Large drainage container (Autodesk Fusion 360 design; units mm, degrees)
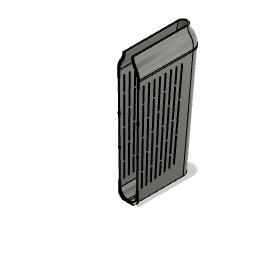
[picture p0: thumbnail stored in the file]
sketch "Schizzo1" plane through (0, 0, 0) normal (0, 1, 0) x axis (1, 0, 0)
  line L1 (12.5, 62.5) -> (12.5, -62.5)
  line L2 (-12.5, -62.5) -> (-12.5, 62.5)
  line L3 (0, 62.5) -> (0, -62.5)
  line L4 (-10, -62.5) -> (-10, 62.5)
  line L5 (10, 62.5) -> (10, -62.5)
  line L6 (0, -75) -> (0, 0)
  line L7 (0, -75) -> (0, 75)
  arc A1 centre (0, 62.5) radius 12.5 clockwise from (-12.5, 62.5) to (12.5, 62.5)
  arc A2 centre (0, -62.5) radius 12.5 clockwise from (12.5, -62.5) to (-12.5, -62.5)
  arc A3 centre (0, -62.5) radius 10 clockwise from (10, -62.5) to (-10, -62.5)
  arc A4 centre (0, 62.5) radius 10 clockwise from (-10, 62.5) to (10, 62.5)
  point P1 (0, 0)
  point P8 (0, 0)
  point P15 (0, 0)
  point P16 (0, -75)
  point P17 (0, 75)
  tangent L1 A1
  tangent A1 L2
  parallel L1 L2
  tangent L2 A2
  tangent L1 A2
  vertical L3
  coincident P1 P8
  midpoint L3 P8
  coincident P8 P15
  midpoint A2 P16
  midpoint A1 P17
  dimension "d3" = -2.5
  dimension "d6" distance L1 L2 = 25
  dimension "d52" distance P16 P17 = 150
work_plane "Piano di lavoro1" AlongDistance 225
sketch "Schizzo6" plane through (0, 225, 0) normal (0, 1, 0) x axis (1, 0, 0)
  line L1 (-12.5, -81.5) -> (-12.5, 81.5)
  line L2 (12.5, 81.5) -> (12.5, -81.5)
  line L3 (0, -81.5) -> (0, 81.5)
  line L4 (15, 81.5) -> (15, -81.5)
  line L5 (-15, -81.5) -> (-15, 81.5)
  line L6 (0, -96.5) -> (0, 0)
  arc A1 centre (0, -81.5) radius 12.5 clockwise from (12.5, -81.5) to (-12.5, -81.5)
  arc A2 centre (0, 81.5) radius 12.5 clockwise from (-12.5, 81.5) to (12.5, 81.5)
  arc A3 centre (0, 81.5) radius 15 clockwise from (-15, 81.5) to (15, 81.5)
  arc A4 centre (0, -81.5) radius 15 clockwise from (15, -81.5) to (-15, -81.5)
  point P1 (0, 0)
  point P8 (0, 0)
  point P15 (0, 0)
  point P16 (0, -96.5)
  tangent L1 A1
  tangent A1 L2
  parallel L1 L2
  tangent L2 A2
  tangent L1 A2
  vertical L3
  coincident P1 P8
  midpoint L3 P8
  coincident P1 P15
  midpoint A4 P16
  dimension "d45" diameter A1 = 25
  dimension "d46" = 2.5
  dimension "d47" distance P15 P16 = 96.5 (= "( 193 / 2 ) * 1 mm")
loft "Loft1" sketch "Schizzo1" + "Schizzo6"
shell "Svuotamento" innerThickness 1.5
extrude "Estrusione1" new body sketch "Schizzo1" profile of L1 A1 L2 A2 along normal blind 2
extrude "Estrusione2" new body sketch "Schizzo1" profile of L1 A1 L2 A2 L5 A3 L4 A4 along normal blind 88 (= "90.00 mm - 2 mm")
sketch "Schizzo3" plane through (0, 0, 0) normal (1, 0, 0) x axis (0, 0, -1)
sketch "Schizzo7" plane through (-12.4985, -0.1389, 0) normal (-0.9999, -0.0111, 0) x axis (0, 0, 1)
  line L1 (62.5, 0.1389) -> (-62.5, 0.1389)
  line L2 (81.5, 225.1528) -> (62.5, 0.1389)
  line L3 (-81.5, 225.1528) -> (81.5, 225.1528)
  line L4 (-62.5, 0.1389) -> (-81.5, 225.1528)
  line L5 (0, 150) -> (0, 0)
  line L6 (100, 150) -> (0, 150)
  line L7 (120, 230) -> (-120, 230)
  line L8 (120, 150) -> (120, 230)
  line L9 (-120, 150) -> (120, 150)
  line L10 (-120, 230) -> (-120, 150)
  point P1 (0, 0)
  point P6 (0, 0)
  coincident P1 P6
  perpendicular L1 L5
  perpendicular L5 L6
  horizontal L7
  vertical L8
  horizontal L9
  vertical L10
extrude "Estrusione7" cut sketch "Schizzo7" profile of L2 L3 L4 L6 L7 L8 L9 L10 along a picked direction blind -110
sketch "Schizzo4" plane through (0, 88, 0) normal (0, 1, 0) x axis (-1, 0, 0)
  line L1 (-10, 62.5) -> (-10, -62.5)
  line L2 (10, -62.5) -> (10, 62.5)
  line L3 (-12.5, -62.5) -> (-12.5, 62.5)
  line L4 (12.5, 62.5) -> (12.5, -62.5)
  arc A1 centre (0, -62.5) radius 10 clockwise from (10, -62.5) to (-10, -62.5)
  arc A2 centre (0, 62.5) radius 10 clockwise from (-10, 62.5) to (10, 62.5)
  circle C1 centre (17, 0) radius 3
  circle C2 centre (14.0385, -4.8188) radius 0.0385
  arc A3 centre (0, 62.5) radius 12.5 clockwise from (-12.5, 62.5) to (12.5, 62.5)
  arc A4 centre (0, -62.5) radius 12.5 clockwise from (12.5, -62.5) to (-12.5, -62.5)
  dimension "d21" diameter C1 = 6
extrude "Estrusione4" cut sketch "Schizzo4" profile of C1 against normal blind 65
sketch "Schizzo5" plane through (0, 0, 0) normal (1, 0, 0) x axis (0, 0, -1)
  line L1 (-62.5, 0) -> (-75.1807, 150.1667)
  line L2 (75.1807, 150.1667) -> (62.5, 0)
  line L3 (-37.6224, 140.713) -> (-37.629, 140.7127)
  line L4 (-30.2514, 19.1836) -> (-36.8819, 140.0496)
  line L5 (-8.2373, 140.036) -> (-6.914, 19.692)
  line L6 (-30.7756, 139.9974) -> (-25.4621, 19.2646)
  line L7 (59.3876, 140.0219) -> (48.7578, 18.766)
  line L8 (-44.6546, 140.8121) -> (-44.6645, 140.8114)
  line L9 (49.3967, 18.0043) -> (49.4099, 18.0031)
  line L10 (45.1203, 140.6769) -> (45.1104, 140.6776)
  line L11 (60.1625, 140.6597) -> (60.1493, 140.6608)
  line L12 (51.8701, 140.0272) -> (42.5711, 18.9002)
  line L13 (-49.4327, 18.045) -> (-49.4196, 18.0462)
  line L14 (43.9861, 18.7916) -> (53.2851, 139.9185)
  line L15 (-45.3183, 140.0592) -> (-36.8301, 18.8002)
  line L16 (-0.7224, 140.0551) -> (-0.7224, 19.8423)
  line L17 (-38.2924, 139.9722) -> (-31.6619, 19.1062)
  line L18 (13.0506, 19.532) -> (15.7004, 140.0061)
  line L19 (-17.8744, 19.4479) -> (-21.8542, 140.0538)
  line L20 (44.3627, 140.0224) -> (36.3898, 19.0258)
  line L21 (-22.58, 140.7332) -> (-22.5833, 140.7331)
  line L22 (43.2183, 18.1455) -> (43.2314, 18.1445)
  line L23 (-24.0542, 19.3265) -> (-29.3677, 140.0594)
  line L24 (-36.0779, 18.1465) -> (-36.068, 18.1472)
  line L25 (30.8587, 18.4361) -> (30.8653, 18.4357)
  line L26 (37.8026, 18.9327) -> (45.7755, 139.9293)
  line L27 (0.6802, 19.8423) -> (0.6802, 140.0551)
  line L28 (-11.6972, 19.5781) -> (-14.347, 140.0521)
  line L29 (30.067, 140.6978) -> (30.0637, 140.6979)
  line L30 (18.5109, 18.7045) -> (18.5142, 18.7043)
  line L31 (-24.7289, 18.5932) -> (-24.7256, 18.5933)
  line L32 (22.5404, 140.7154) -> (22.5371, 140.7155)
  line L33 (-15.7526, 140.0212) -> (-13.1028, 19.5472)
  line L34 (-42.5981, 18.9327) -> (-51.8971, 140.0597)
  line L35 (-43.2584, 18.177) -> (-43.2452, 18.178)
  line L36 (6.8673, 19.6786) -> (8.1906, 140.0226)
  line L37 (-48.7807, 18.8079) -> (-59.4105, 140.0639)
  line L38 (24.6884, 18.5605) -> (24.6916, 18.5603)
  line L39 (36.8258, 140.0425) -> (30.1953, 19.1765)
  line L40 (-30.1009, 140.7308) -> (-30.1042, 140.7306)
  line L41 (-35.4143, 18.8994) -> (-43.9024, 140.1583)
  line L42 (37.045, 18.2781) -> (37.0549, 18.2775)
  line L43 (52.638, 140.6733) -> (52.6248, 140.6743)
  line L44 (50.1715, 18.642) -> (60.8014, 139.898)
  line L45 (21.8113, 140.0361) -> (17.8314, 19.4302)
  line L46 (-60.1722, 140.7028) -> (-60.1854, 140.7016)
  line L47 (-18.5571, 18.7221) -> (-18.5538, 18.7222)
  line L48 (37.5728, 140.7056) -> (37.5662, 140.7059)
  line L49 (6.7847, 140.0381) -> (5.4614, 19.694)
  line L50 (-5.5082, 19.7074) -> (-6.8315, 140.0515)
  line L51 (14.2948, 140.037) -> (11.645, 19.5629)
  line L52 (-30.9214, 18.4428) -> (-30.9149, 18.4432)
  line L53 (-52.6518, 140.7068) -> (-52.6649, 140.7058)
  line L54 (-60.8243, 139.9399) -> (-50.1944, 18.6839)
  line L55 (-23.2627, 140.0073) -> (-19.2829, 19.4015)
  line L56 (25.4249, 19.2317) -> (30.7384, 139.9646)
  line L57 (19.2399, 19.3838) -> (23.2198, 139.9896)
  line L58 (29.3305, 140.0265) -> (24.017, 19.2937)
  line L59 (31.6057, 19.0991) -> (38.2362, 139.9651)
  line L60 (-53.3121, 139.9511) -> (-44.0131, 18.8241)
  line L61 (-60, 58) -> (61.3605, 60)
  line L62 (67.6571, 100) -> (-67.6571, 100)
  line L63 (67.6571, 98) -> (67.6571, 100)
  line L64 (-67.6571, 98) -> (67.6571, 98)
  line L65 (-67.6571, 100) -> (-67.6571, 98)
  line L66 (67.6571, 98) -> (-67.6571, 100)
  line L67 (-67.6571, 98) -> (67.6571, 100)
  line L68 (0, 19) -> (0, 0)
  line L69 (-0.0211, 139.1394) -> (-0.0211, 19.1394)
  line L70 (0, 59) -> (0, 19)
  line L71 (0, 99) -> (0, 19)
  line L72 (165.9789, 19) -> (0, 19)
  line L73 (-75, 60) -> (75, 60)
  line L74 (-75, 58) -> (-75, 60)
  line L75 (75, 58) -> (-75, 58)
  line L76 (75, 60) -> (75, 58)
  line L77 (-75, 58) -> (75, 60)
  line L78 (75, 58) -> (-75, 60)
  line L79 (0, 39) -> (0, 19)
  line L80 (60, 40) -> (-60, 40)
  line L81 (60, 38) -> (60, 40)
  line L82 (-60, 38) -> (60, 38)
  line L83 (-60, 40) -> (-60, 38)
  line L84 (60, 38) -> (-60, 40)
  line L85 (-60, 38) -> (60, 40)
  line L86 (0, 79) -> (0, 19)
  line L87 (60, 80) -> (-60, 80)
  line L88 (60, 78) -> (60, 80)
  line L89 (-60, 78) -> (60, 78)
  line L90 (-60, 80) -> (-60, 78)
  line L91 (60, 78) -> (-60, 80)
  line L92 (-60, 78) -> (60, 80)
  line L93 (0, 119) -> (0, 19)
  line L94 (65, 120) -> (-65, 120)
  line L95 (65, 118) -> (65, 120)
  line L96 (-65, 118) -> (65, 118)
  line L97 (-65, 120) -> (-65, 118)
  line L98 (65, 118) -> (-65, 120)
  line L99 (-65, 118) -> (65, 120)
  line L100 (-50.8088, 25.6928) -> (-0.0211, 19.1394)
  line L101 (50.7896, 25.6928) -> (-0.0211, 19.1394)
  curve K1 (-24.7565, 19.2956) -> (0, 19)
  curve K2 (-50.8088, 25.6928) -> (-24.7565, 19.2956)
  curve K3 (-50.8088, 25.6928) -> (0, 19)
  curve K4 (50.8088, 25.6928) -> (0, 19)
  curve K5 (24.7565, 19.2956) -> (0, 19)
  curve K6 (50.8088, 25.6928) -> (24.7565, 19.2956)
  line L102 (-75.1807, 150.1667) -> (75.1807, 150.1667)
  closed curve K7 centre (-0.0203, 140.0559)
  arc A1 centre (52.5842, 139.9723) radius 0.703 between (53.2851, 139.9185) and (52.638, 140.6733)
  arc A2 centre (-43.3122, 18.8779) radius 0.703 between (-44.0131, 18.8241) and (-43.2584, 18.177)
  arc A3 centre (-52.598, 140.0059) radius 0.703 between (-51.8971, 140.0597) and (-52.6518, 140.7068)
  arc A4 centre (22.5172, 140.0128) radius 0.703 between (23.2198, 139.9896) and (22.5404, 140.7154)
  arc A5 centre (12.3478, 19.5475) radius 0.703 between (12.3324, 18.8447) and (13.0506, 19.532)
  arc A6 centre (7.4876, 140.0304) radius 0.703 between (7.4954, 140.7333) and (6.7847, 140.0381)
  arc A7 centre (30.8972, 19.138) radius 0.703 between (30.1953, 19.1765) and (30.8587, 18.4361)
  arc A8 centre (52.571, 139.9734) radius 0.703 between (52.6248, 140.6743) and (51.8701, 140.0272)
  arc A9 centre (43.2721, 18.8464) radius 0.703 between (42.5711, 18.9002) and (43.2183, 18.1455)
  arc A10 centre (60.0879, 139.9605) radius 0.703 between (60.1493, 140.6608) and (59.3876, 140.0219)
  arc A11 centre (37.0912, 18.9796) radius 0.703 between (36.3898, 19.0258) and (37.045, 18.2781)
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  point P203 (0.6802, 59)
  point P208 (0, 99)
  point P1 (0, 0)
  point P209 (0, 0)
  point P213 (0, 99)
  point P219 (0, 59)
  point P212 (0, 59)
  point P225 (0, 39)
  point P220 (0, 39)
  point P231 (0, 79)
  point P226 (0, 79)
  point P237 (0, 119)
  point P232 (0, 119)
  point P238 (-50.8088, 25.6928)
  point P239 (50.7896, 25.6928)
  point P115 (-24.7565, 19.2956)
  point P240 (-24.7565, 19.2956)
  point P210 (0, 19)
  point P241 (0, 19)
  point P242 (50.8088, 25.6928)
  point P204 (-67.6571, 100)
  point P207 (-67.6571, 98)
  point P171 (-0.0211, 19.1394)
  point P211 (-0.0211, 139.1394)
  point P217 (-75, 58)
  point P218 (75, 58)
  point P216 (-75, 60)
  point P223 (60, 38)
  point P224 (-60, 38)
  point P222 (60, 40)
  point P229 (60, 78)
  point P230 (-60, 78)
  point P228 (60, 80)
  point P235 (65, 118)
  point P236 (-65, 118)
  point P234 (65, 120)
  coincident L27 P203
  horizontal L62
  perpendicular L62 L63
  parallel L62 L64
  parallel L63 L65
  coincident L66 P208
  coincident L67 P208
  coincident P1 P209
  parallel L69 L70
  horizontal L72
  vertical L71
  coincident P208 P213
  horizontal L73
  perpendicular L73 L74
  parallel L73 L75
  parallel L74 L76
  coincident L77 P219
  coincident L78 P219
  coincident P212 P219
  perpendicular L72 L79
  horizontal L80
  perpendicular L80 L81
  parallel L80 L82
  parallel L81 L83
  coincident L84 P225
  coincident L85 P225
  coincident P220 P225
  horizontal L87
  perpendicular L87 L88
  parallel L87 L89
  parallel L88 L90
  coincident L91 P231
  coincident L92 P231
  coincident P226 P231
  horizontal L94
  perpendicular L94 L95
  parallel L94 L96
  parallel L95 L97
  coincident L98 P237
  coincident L99 P237
  coincident P232 P237
  coincident L54 P238
  coincident L44 P239
  coincident P115 P240
  symmetric P210 L93 P241
  symmetric L93 P238 P242
  symmetric L93 K3 K4
  dimension "d82" distance P204 P207 = 2
  dimension "d84" distance P209 P210 = 19
  dimension "d85" distance P171 P211 = 120
  dimension "d86" distance P210 P212 = 40
  dimension "d88" distance P210 P213 = 80
  dimension "d89" distance P217 P218 = 150
  dimension "d90" distance P216 P217 = 2
  dimension "d91" distance P210 P220 = 20
  dimension "d92" distance P223 P224 = 120
  dimension "d93" distance P222 P223 = 2
  dimension "d94" distance P210 P226 = 60
  dimension "d95" distance P229 P230 = 120
  dimension "d96" distance P228 P229 = 2
  dimension "d97" distance P210 P232 = 100
  dimension "d98" distance P235 P236 = 130
  dimension "d99" distance P234 P235 = 2
extrude "Estrusione5" cut sketch "Schizzo5" distance 100
fillet "Raccordo9" radius 0.7
fillet "Raccordo8" radius 0.7 0.7 0.7 0.7 0.7 0.7 0.7 0.7 0.7 0.7
fillet "Raccordo7" radius 10
sketch "Schizzo9" plane through (-12.4985, -0.1389, 0) normal (-0.9999, -0.0111, 0) x axis (0, 0, 1)
  line L1 (38.1057, 57.4913) -> (35.7271, 23.5086)
  line L2 (44.6645, 140.959) -> (44.6546, 140.9597)
  line L3 (42.5597, 100.7962) -> (45.3183, 140.2067)
  line L4 (14.347, 140.1996) -> (13.4818, 100.8605)
  line L5 (14.8874, 100.8297) -> (15.7526, 140.1687)
  line L6 (-6.1323, 80.8516) -> (-6.5347, 117.4538)
  line L7 (-7.9406, 117.4384) -> (-7.5382, 80.8362)
  line L8 (-38.2362, 140.1127) -> (-37.1773, 120.808)
  line L9 (-37.5662, 140.8535) -> (-37.5728, 140.8531)
  line L10 (-35.7668, 120.8847) -> (-36.8258, 140.19)
  line L11 (-60.1493, 140.8084) -> (-60.1625, 140.8072)
  line L12 (-49.4187, 26.4457) -> (-52.1412, 57.5036)
  line L13 (-53.5551, 57.3813) -> (-50.833, 26.3282)
  line L14 (-24.1151, 21.6631) -> (-25.691, 57.4732)
  line L15 (-27.0989, 57.4116) -> (-25.523, 21.6027)
  line L16 (-30.0637, 140.8455) -> (-30.067, 140.8453)
  line L17 (6.5814, 117.4538) -> (6.1789, 80.8516)
  line L18 (7.5848, 80.8362) -> (7.9872, 117.4384)
  line L19 (31.2474, 37.4795) -> (30.4305, 22.5888)
  line L20 (37.629, 140.8602) -> (37.6224, 140.8606)
  line L21 (32.8444, 40.803) -> (34.8522, 77.4053)
  line L22 (44.4667, 24.8733) -> (45.4274, 37.3876)
  line L23 (44.0123, 37.4948) -> (43.0513, 24.9762)
  line L24 (52.6649, 140.8533) -> (52.6518, 140.8544)
  line L25 (22.6248, 120.8232) -> (23.2627, 140.1548)
  line L26 (21.8542, 140.2013) -> (21.2163, 120.8694)
  line L27 (22.5833, 140.8807) -> (22.58, 140.8808)
  line L28 (-12.5502, 60.858) -> (-13.3552, 97.4603)
  line L29 (-13.881, 57.427) -> (-13.0655, 20.3489)
  line L30 (-40.3277, 57.3964) -> (-38.1005, 23.5951)
  line L31 (-45.1104, 140.8252) -> (-45.1203, 140.8245)
  line L32 (-39.1389, 60.8887) -> (-41.5506, 97.4909)
  line L33 (-52.6248, 140.8218) -> (-52.638, 140.8208)
  line L34 (-44.2488, 40.895) -> (-47.0586, 77.4972)
  line L35 (-45.4029, 37.3876) -> (-44.4418, 24.8679)
  line L36 (-19.8304, 37.4181) -> (-19.2848, 20.8837)
  line L37 (-22.5371, 140.8631) -> (-22.5404, 140.8629)
  line L38 (-17.8763, 20.9289) -> (-18.4219, 37.4643)
  line L39 (0.7224, 100.8451) -> (0.7224, 140.1537)
  line L40 (-0.6802, 140.157) -> (-0.6802, 100.8451)
  line L41 (25.7268, 57.4732) -> (24.151, 21.6678)
  line L42 (30.1042, 140.8782) -> (30.1009, 140.8783)
  line L43 (29.0447, 100.8143) -> (30.7756, 140.1449)
  line L44 (57.379, 100.784) -> (60.8243, 140.0874)
  line L45 (52.1604, 57.5036) -> (49.4383, 26.4504)
  line L46 (60.1854, 140.8492) -> (60.1722, 140.8503)
  line L47 (-62.5, 0.1389) -> (-75.1542, 150)
  line L48 (62.5, 0.1389) -> (-62.5, 0.1389)
  line L49 (75.1542, 150) -> (62.5, 0.1389)
  line L50 (52.877, 58.1425) -> (52.8578, 58.1425)
  line L51 (38.8234, 58.1425) -> (38.804, 58.1425)
  line L52 (28.1958, 98.1449) -> (28.1865, 98.1449)
  line L53 (26.5757, 60.1426) -> (26.585, 60.1426)
  line L54 (14.1128, 98.1449) -> (14.1068, 98.1449)
  line L55 (13.3018, 60.1426) -> (13.3078, 60.1426)
  line L56 (-52.8386, 58.1425) -> (-52.8578, 58.1425)
  line L57 (-42.2491, 98.1449) -> (-42.265, 98.1449)
  line L58 (-39.8533, 60.1426) -> (-39.8374, 60.1426)
  line L59 (-28.1507, 98.1449) -> (-28.16, 98.1449)
  line L60 (-26.5492, 60.1426) -> (-26.54, 60.1426)
  line L61 (-14.055, 98.1449) -> (-14.061, 98.1449)
  line L62 (-13.2559, 60.1426) -> (-13.25, 60.1426)
  line L63 (0.0224, 58.1425) -> (0.0198, 58.1425)
  line L64 (56.6624, 100.1451) -> (56.6816, 100.1451)
  line L65 (41.6234, 98.1449) -> (41.604, 98.1449)
  line L66 (39.042, 60.1426) -> (39.0614, 60.1426)
  line L67 (26.4354, 58.1425) -> (26.4261, 58.1425)
  line L68 (13.233, 58.1425) -> (13.227, 58.1425)
  line L69 (0.0198, 100.1451) -> (0.0224, 100.1451)
  line L70 (-14.1357, 100.1451) -> (-14.1298, 100.1451)
  line L71 (-28.3097, 100.1451) -> (-28.3004, 100.1451)
  line L72 (-42.489, 100.1451) -> (-42.4731, 100.1451)
  line L73 (-56.3451, 98.1449) -> (-56.3644, 98.1449)
  line L74 (-53.1558, 60.1426) -> (-53.1366, 60.1426)
  line L75 (-56.6624, 100.1451) -> (-56.6432, 100.1451)
  line L76 (-39.6133, 58.1425) -> (-39.6292, 58.1425)
  line L77 (-26.3903, 58.1425) -> (-26.3996, 58.1425)
  line L78 (-13.1752, 58.1425) -> (-13.1812, 58.1425)
  line L79 (0.0224, 98.1449) -> (0.0198, 98.1449)
  line L80 (0.0198, 60.1426) -> (0.0224, 60.1426)
  line L81 (14.1816, 100.1451) -> (14.1876, 100.1451)
  line L82 (28.3362, 100.1451) -> (28.3454, 100.1451)
  line L83 (41.842, 100.1451) -> (41.8614, 100.1451)
  line L84 (56.3836, 98.1449) -> (56.3643, 98.1449)
  line L85 (53.1558, 60.1426) -> (53.1751, 60.1426)
  line L86 (21.916, 120.1463) -> (21.9252, 120.1463)
  line L87 (-19.1215, 38.1412) -> (-19.1308, 38.1412)
  line L88 (-36.4783, 120.1463) -> (-36.4658, 120.1463)
  line L89 (21.3049, 80.8208) -> (22.5127, 117.423)
  line L90 (20.596, 80.1438) -> (20.6053, 80.1438)
  line L91 (21.1041, 117.4692) -> (19.8964, 80.8669)
  line L92 (21.813, 118.1462) -> (21.8038, 118.1462)
  line L93 (-6.8382, 80.1438) -> (-6.8322, 80.1438)
  line L94 (-7.2347, 118.1462) -> (-7.2407, 118.1462)
  line L95 (19.985, 40.8183) -> (21.1927, 77.4206)
  line L96 (19.2761, 40.1413) -> (19.2853, 40.1413)
  line L97 (19.7842, 77.4667) -> (18.5764, 40.8645)
  line L98 (20.4931, 78.1437) -> (20.4838, 78.1437)
  line L99 (-44.966, 40.1413) -> (-44.9468, 40.1413)
  line L100 (-47.7566, 78.1437) -> (-47.7758, 78.1437)
  line L101 (0.7224, 20.0281) -> (0.7224, 57.4424)
  line L102 (-0.6802, 57.4424) -> (-0.6802, 20.0313)
  line L103 (-55.9459, 100.9062) -> (-59.3876, 140.1694)
  line L104 (-60.8014, 140.0455) -> (-57.3598, 100.784)
  line L105 (-31.3782, 40.8797) -> (-33.386, 77.482)
  line L106 (-32.0897, 40.1413) -> (-32.0771, 40.1413)
  line L107 (-34.7964, 77.4053) -> (-32.7886, 40.803)
  line L108 (-34.0849, 78.1437) -> (-34.0975, 78.1437)
  line L109 (-57.0617, 97.3838) -> (-53.8532, 60.7815)
  line L110 (-52.4393, 60.9038) -> (-55.6478, 97.506)
  line L111 (32.1328, 40.1413) -> (32.1454, 40.1413)
  line L112 (34.1532, 78.1437) -> (34.1407, 78.1437)
  line L113 (6.8789, 80.1438) -> (6.8848, 80.1438)
  line L114 (7.2873, 118.1462) -> (7.2813, 118.1462)
  line L115 (-19.854, 80.8669) -> (-21.0618, 117.4692)
  line L116 (-20.5629, 80.1438) -> (-20.5536, 80.1438)
  line L117 (-22.4703, 117.423) -> (-21.2625, 80.8208)
  line L118 (-21.7614, 118.1462) -> (-21.7707, 118.1462)
  line L119 (55.667, 97.506) -> (52.4585, 60.9038)
  line L120 (53.8724, 60.7815) -> (57.0809, 97.3838)
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chamfer "Smusso7" distance 5
work_plane "Piano di lavoro2" AlongDistance 25
sketch "Schizzo12" plane through (-1.6666, 149.9907, 0) normal (-0.0111, 0.9999, 0) x axis (0, 0, 1)
  curve K1 (-75.1807, 15.8361) -> (-75.1542, -12.4992)
  line L1 (75.1542, -12.4992) -> (-75.1542, -12.4992)
  curve K2 (75.1542, -12.4992) -> (75.1807, 15.8361)
  line L2 (-75.1807, 15.8361) -> (75.1807, 15.8361)
  curve K3 (75.1779, 14.3357) -> (75.1542, -10.9992)
  line L3 (-75.1542, -10.9992) -> (75.1542, -10.9992)
  curve K4 (-75.1542, -10.9992) -> (-75.1779, 14.3357)
  line L4 (75.1779, 14.3357) -> (-75.1779, 14.3357)
sketch "Schizzo14" plane through (-0.276, 175.0077, 0) normal (-0.0111, 0.9999, 0) x axis (0, 0, 1)
  curve K1 (-75.1808, 14.1676) -> (-75.1542, -14.1676)
  line L1 (75.1541, -14.1676) -> (-75.1542, -14.1676)
  curve K2 (75.1541, -14.1676) -> (75.1807, 14.1676)
  line L2 (-75.1808, 14.1676) -> (75.1807, 14.1676)
  curve K3 (75.1779, 12.6673) -> (75.1541, -12.6676)
  line L3 (-75.1542, -12.6676) -> (75.1541, -12.6676)
  curve K4 (-75.1542, -12.6676) -> (-75.178, 12.6673)
  line L4 (75.1779, 12.6673) -> (-75.178, 12.6673)
  curve K5 (75.1779, 6.6673) -> (75.1541, -6.6676)
  line L5 (75.1779, 6.6673) -> (-75.178, 6.6673)
  curve K6 (-75.1542, -6.6676) -> (-75.178, 6.6673)
  line L6 (-75.1542, -6.6676) -> (75.1541, -6.6676)
  line L7 (0, 6.6673) -> (0, 0)
  line L8 (0, -6.6676) -> (0, 0)
  point P1 (0, 0)
  point P14 (0, 0)
  point P15 (0, 6.6673)
  point P16 (0, 0)
  point P17 (0, -6.6676)
  coincident P1 P14
  midpoint L5 P15
  coincident P1 P16
  midpoint L6 P17
  dimension "d126" = 6
sketch "Schizzo15" plane through (0, 0, 0) normal (1, 0, 0) x axis (0, 0, -1)
  line L1 (89.3342, 150.0093) -> (75.4756, 4.9773)
  line L2 (0, 210) -> (0, 0)
  curve K1 (90.6842, 164.1368) -> (89.3342, 150.0093)
  curve K2 (81.8222, 165.0217) -> (90.6842, 164.1368)
  curve K3 (81.8222, 175.0108) -> (81.8222, 165.0217)
  curve K4 (81.8222, 175.0108) -> (89.3342, 150.0093)
  curve K5 (-81.8222, 175.0108) -> (-89.3342, 150.0093)
  curve K6 (-90.6842, 164.1368) -> (-89.3342, 150.0093)
  curve K7 (-81.8222, 165.0217) -> (-90.6842, 164.1368)
  curve K8 (-81.8222, 175.0108) -> (-81.8222, 165.0217)
  point P1 (0, 0)
  point P4 (0, 0)
  point P6 (81.8222, 175.0108)
  point P9 (81.8222, 175.0108)
  point P3 (89.3342, 150.0093)
  point P10 (-89.3342, 150.0093)
  point P11 (-81.8222, 175.0108)
  coincident P1 P4
  vertical L2
  coincident P6 P9
  vertical K3
  parallel L1 K1
  symmetric P3 L2 P10
  symmetric L2 P9 P11
  symmetric L2 K4 K5
sketch "Schizzo16" plane through (0, 0, 0) normal (0, 0, 1) x axis (1, 0, 0)
  curve K1 (12.5556, 4.9996) -> (-12.5556, 4.9996)
  line L1 (-14.165, 149.8519) -> (-12.5556, 4.9996)
  line L2 (14.1685, 150.1667) -> (-14.165, 149.8519)
  line L3 (12.5556, 4.9996) -> (14.1685, 150.1667)
  curve K2 (14.3227, 164.0468) -> (14.1685, 150.1667)
  curve K3 (6.3909, 163.867) -> (14.3227, 164.0468)
  curve K4 (6.3909, 175.0818) -> (6.3909, 163.867)
  curve K5 (6.3909, 175.0818) -> (14.1685, 150.1667)
  line L4 (0, 210) -> (0, 0)
  curve K6 (-14.3192, 163.732) -> (-14.165, 149.8519)
  curve K7 (-6.9432, 163.7188) -> (-14.3192, 163.732)
  curve K8 (-6.9432, 174.9337) -> (-6.9432, 163.7188)
  curve K9 (-6.9432, 174.9337) -> (-14.165, 149.8519)
  point P6 (6.3909, 175.0818)
  point P10 (6.3909, 175.0818)
  point P1 (0, 0)
  point P11 (0, 0)
  point P7 (-6.9432, 174.9337)
  point P15 (-6.9432, 174.9337)
  point P5 (14.1685, 150.1667)
  point P8 (14.3227, 164.0468)
  point P4 (-14.165, 149.8519)
  point P13 (-14.3192, 163.732)
  point P9 (6.3909, 163.867)
  point P14 (-6.9432, 163.7188)
  coincident P6 P10
  parallel L3 K2
  vertical K4
  coincident P1 P11
  vertical L4
  coincident P7 P15
  vertical K8
  parallel L1 K6
  dimension "d127" distance P5 P8 = 13.8801
  dimension "d128" distance P4 P13 = 13.8801 (= "d127")
  dimension "d129" distance L2 P9 = 13.7858
  dimension "d130" distance L2 P14 = 13.7858 (= "d129")
loft "Loft2"
thicken "Ispessisci" Thickness -1.5
sketch "Schizzo17" plane through (0, 0, 0) normal (0, 0, 1) x axis (1, 0, 0)
sketch "Schizzo18" plane through (-0.276, 175.0077, 0) normal (-0.0111, 0.9999, 0) x axis (0, 0, 1)
  line L1 (94.2699, 22.834) -> (-94.2699, 22.834)
  line L2 (94.2699, -22.834) -> (94.2699, 22.834)
  line L3 (-94.2699, -22.834) -> (94.2699, -22.834)
  line L4 (-94.2699, 22.834) -> (-94.2699, -22.834)
  line L5 (94.2699, -22.834) -> (-94.2699, 22.834)
  line L6 (-94.2699, -22.834) -> (94.2699, 22.834)
  point P6 (0, 0)
  point P1 (0, 0)
  horizontal L1
  perpendicular L1 L2
  parallel L1 L3
  parallel L2 L4
  coincident L5 P6
  coincident L6 P6
  coincident P1 P6
extrude "Estrusione8" cut sketch "Schizzo18" profile of L1 L2 L3 L4 distance -0.5
sketch "Schizzo21" plane through (-1.6666, 149.9907, 0) normal (-0.0111, 0.9999, 0) x axis (0, 0, 1)
  curve K1 (-75.1807, 15.8361) -> (-75.1542, -12.4992)
  line L1 (75.1542, -12.4992) -> (-75.1542, -12.4992)
  curve K2 (75.1542, -12.4992) -> (75.1807, 15.8361)
  line L2 (-75.1807, 15.8361) -> (75.1807, 15.8361)
  curve K3 (75.1779, 14.3357) -> (75.1542, -10.9992)
  line L3 (-75.1542, -10.9992) -> (75.1542, -10.9992)
  curve K4 (-75.1542, -10.9992) -> (-75.1779, 14.3357)
  line L4 (75.1779, 14.3357) -> (-75.1779, 14.3357)
  line L5 (90, 20) -> (-90, 20)
  line L6 (90, -20) -> (90, 20)
  line L7 (-90, -20) -> (90, -20)
  line L8 (-90, 20) -> (-90, -20)
  line L9 (90, -20) -> (-90, 20)
  line L10 (-90, -20) -> (90, 20)
  point P14 (0, 0)
  point P1 (0, 0)
  horizontal L5
  perpendicular L5 L6
  parallel L5 L7
  parallel L6 L8
  coincident L9 P14
  coincident L10 P14
  coincident P1 P14
extrude "Estrusione9" cut sketch "Schizzo21" profile of K1 L1 K2 L2 K3 L3 K4 L4 L5 L6 L7 L8 against normal blind 0.5 and along normal blind 0.2
move "Sposta"
sketch "Schizzo19" plane through (0, 0, 0) normal (0, 0, 1) x axis (1, 0, 0)
  curve K1 (12.5556, 4.9996) -> (-12.5556, 4.9996)
  line L1 (-14.165, 149.8519) -> (-12.5556, 4.9996)
  line L2 (14.1685, 150.1667) -> (-14.165, 149.8519)
  line L3 (12.5556, 4.9996) -> (14.1685, 150.1667)
  line L4 (-14.1428, 147.8519) -> (-14.165, 149.8519)
  line L5 (-13.3928, 147.8602) -> (-14.1428, 147.8519)
  line L6 (-13.415, 149.8602) -> (-13.3928, 147.8602)
  line L7 (-14.165, 149.8519) -> (-13.415, 149.8602)
  line L8 (-13.365, 149.8602) -> (-13.415, 149.8602)
  line L9 (-13.365, 147.8619) -> (-13.365, 149.8602)
  line L10 (-13.415, 147.8619) -> (-13.365, 147.8619)
  line L11 (-13.415, 149.8602) -> (-13.415, 147.8619)
  line L12 (-12.6651, 149.8685) -> (-11.1265, 11.3889)
  line L13 (-11.1265, 11.3889) -> (-12.6651, 149.8685)
  line L14 (-12.5557, 140.0212) -> (-12.1186, 100.6846)
  line L15 (-12.5557, 140.0212) -> (-12.5637, 140.7396)
  line L16 (-12.119, 100.7154) -> (-12.556, 140.0521)
  line L17 (-12.119, 100.7154) -> (-12.111, 100)
  line L18 (-12.1186, 100.6846) -> (-12.111, 100)
  line L19 (-12.5555, 140.0073) -> (-12.3408, 120.6769)
  line L20 (-12.5555, 140.0073) -> (-12.5636, 140.7331)
  line L21 (-12.5636, 140.7332) -> (-12.5636, 140.7331)
  line L22 (-12.5561, 140.0538) -> (-12.5636, 140.7336)
  line L23 (-12.3413, 120.7231) -> (-12.5561, 140.0538)
  line L24 (-12.3413, 120.7231) -> (-12.3332, 120)
  line L25 (-12.3408, 120.6769) -> (-12.3332, 120)
  line L26 (-11.2759, 24.8358) -> (-11.4149, 37.3536)
  line L27 (-11.2759, 24.8358) -> (-11.2675, 24.0822)
  line L28 (-11.2677, 24.1022) -> (-11.2677, 24.098)
  line L29 (-11.2677, 24.1022) -> (-11.2747, 24.7329)
  line L30 (-11.4138, 37.2464) -> (-11.2747, 24.7329)
  line L31 (-11.4221, 38) -> (-11.4138, 37.2464)
  line L32 (-11.4221, 38) -> (-11.4149, 37.3536)
  line L33 (-12.5558, 140.0272) -> (-12.3416, 120.7536)
  line L34 (-12.5558, 140.0272) -> (-12.563, 140.6763)
  line L35 (-12.5629, 140.6733) -> (-12.563, 140.6743)
  line L36 (-12.5546, 139.9185) -> (-12.5629, 140.6733)
  line L37 (-12.3404, 120.6464) -> (-12.5546, 139.9185)
  line L38 (-12.3404, 120.6464) -> (-12.3332, 120)
  line L39 (-12.3416, 120.7536) -> (-12.3332, 120)
  line L40 (-12.5559, 140.037) -> (-12.119, 100.7154)
  line L41 (-12.5555, 140.0061) -> (-12.5635, 140.7245)
  line L42 (-12.1186, 100.6846) -> (-12.5555, 140.0061)
  line L43 (-12.1186, 100.6846) -> (-12.111, 100)
  line L44 (-12.119, 100.7154) -> (-12.111, 100)
  line L45 (-12.3028, 117.2617) -> (-11.8961, 80.6617)
  line L46 (-12.311, 118) -> (-12.3028, 117.2617)
  line L47 (-12.311, 118) -> (-12.3037, 117.3383)
  line L48 (-11.897, 80.7383) -> (-12.3037, 117.3383)
  line L49 (-11.897, 80.7383) -> (-11.8888, 80)
  line L50 (-11.8961, 80.6617) -> (-11.8888, 80)
  line L51 (-12.3032, 117.2923) -> (-11.8965, 80.6923)
  line L52 (-12.311, 118) -> (-12.3032, 117.2923)
  line L53 (-12.311, 118) -> (-12.3033, 117.3077)
  line L54 (-11.8967, 80.7077) -> (-12.3033, 117.3077)
  line L55 (-11.8967, 80.7077) -> (-11.8888, 80)
  line L56 (-11.8965, 80.6923) -> (-11.8888, 80)
  line L57 (-12.5558, 140.0265) -> (-12.1191, 100.7308)
  line L58 (-12.5558, 140.0265) -> (-12.5632, 140.6986)
  line L59 (-12.5632, 140.6978) -> (-12.5632, 140.6979)
  line L60 (-12.5551, 139.9646) -> (-12.5632, 140.6978)
  line L61 (-12.1185, 100.6692) -> (-12.5551, 139.9646)
  line L62 (-12.1185, 100.6692) -> (-12.111, 100)
  line L63 (-12.1191, 100.7308) -> (-12.111, 100)
  line L64 (-11.6373, 57.3611) -> (-11.2922, 26.3052)
  line L65 (-11.6444, 58) -> (-11.6373, 57.3611)
  line L66 (-11.6444, 58) -> (-11.6359, 57.2389)
  line L67 (-11.2909, 26.1877) -> (-11.6359, 57.2389)
  line L68 (-11.2909, 26.1877) -> (-11.284, 25.5687)
  line L69 (-11.284, 25.5639) -> (-11.284, 25.5687)
  line L70 (-11.2837, 25.544) -> (-11.2922, 26.3052)
  line L71 (-11.6371, 57.346) -> (-11.2615, 23.5438)
  line L72 (-11.6444, 58) -> (-11.6371, 57.346)
  line L73 (-11.6444, 58) -> (-11.6361, 57.254)
  line L74 (-11.2605, 23.4548) -> (-11.6361, 57.254)
  line L75 (-11.2605, 23.4548) -> (-11.2534, 22.8128)
  line L76 (-11.2533, 22.8098) -> (-11.2534, 22.8128)
  line L77 (-11.2532, 22.7978) -> (-11.2615, 23.5438)
  line L78 (-11.6737, 60.6389) -> (-12.0803, 97.2389)
  line L79 (-11.6737, 60.6389) -> (-11.6666, 60)
  line L80 (-11.675, 60.7611) -> (-11.6666, 60)
  line L81 (-12.0817, 97.3611) -> (-11.675, 60.7611)
  line L82 (-12.0888, 98) -> (-12.0817, 97.3611)
  line L83 (-12.0888, 98) -> (-12.0803, 97.2389)
  line L84 (-11.6747, 60.7308) -> (-12.0814, 97.3308)
  line L85 (-11.6747, 60.7308) -> (-11.6666, 60)
  line L86 (-11.674, 60.6692) -> (-11.6666, 60)
  line L87 (-12.0807, 97.2692) -> (-11.674, 60.6692)
  line L88 (-12.0888, 98) -> (-12.0807, 97.2692)
  line L89 (-12.0888, 98) -> (-12.0814, 97.3308)
  line L90 (-11.6738, 60.654) -> (-12.0805, 97.254)
  line L91 (-11.6738, 60.654) -> (-11.6666, 60)
  line L92 (-11.6749, 60.746) -> (-11.6666, 60)
  line L93 (-12.0815, 97.346) -> (-11.6749, 60.746)
  line L94 (-12.0888, 98) -> (-12.0815, 97.346)
  line L95 (-12.0888, 98) -> (-12.0805, 97.254)
  line L96 (-11.8591, 77.3231) -> (-11.4524, 40.7231)
  line L97 (-11.8666, 78) -> (-11.8591, 77.3231)
  line L98 (-11.8666, 78) -> (-11.8585, 77.2769)
  line L99 (-11.4519, 40.6769) -> (-11.8585, 77.2769)
  line L100 (-11.4519, 40.6769) -> (-11.4444, 40)
  line L101 (-11.4524, 40.7231) -> (-11.4444, 40)
  line L102 (-11.2391, 21.5276) -> (-11.6369, 57.3308)
  line L103 (-11.2391, 21.5276) -> (-11.231, 20.7968)
  line L104 (-11.2311, 20.8039) -> (-11.231, 20.8027)
  line L105 (-11.2311, 20.8039) -> (-11.2384, 21.4672)
  line L106 (-11.6362, 57.2692) -> (-11.2384, 21.4672)
  line L107 (-11.6444, 58) -> (-11.6362, 57.2692)
  line L108 (-11.6444, 58) -> (-11.6369, 57.3308)
  line L109 (-11.2596, 23.3683) -> (-11.6371, 57.3489)
  line L110 (-11.2596, 23.3683) -> (-11.2512, 22.6194)
  line L111 (-11.2514, 22.6345) -> (-11.2514, 22.6309)
  line L112 (-11.2514, 22.6345) -> (-11.2585, 23.2742)
  line L113 (-11.636, 57.2511) -> (-11.2585, 23.2742)
  line L114 (-11.6444, 58) -> (-11.636, 57.2511)
  line L115 (-11.6444, 58) -> (-11.6371, 57.3489)
  line L116 (-11.6367, 57.3154) -> (-11.2248, 20.2392)
  line L117 (-11.6444, 58) -> (-11.6367, 57.3154)
  line L118 (-11.6444, 58) -> (-11.6364, 57.2846)
  line L119 (-11.2244, 20.2088) -> (-11.6364, 57.2846)
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  point P7 (-14.1428, 147.8519)
  point P4 (-14.165, 149.8519)
  point P6 (-14.165, 149.8519)
  point P270 (-12.6429, 147.8685)
  point P271 (-13.365, 149.8608)
  point P273 (-12.644, 147.9685)
  point P281 (-12.664, 149.7685)
  point P8 (-13.3928, 147.8602)
  point P9 (-13.415, 149.8602)
  point P10 (-13.365, 149.8602)
  point P272 (-14.1439, 147.9519)
  point P280 (-14.1639, 149.7519)
  perpendicular L4 L5
  parallel L4 L6
  parallel L5 L7
  coincident L1 P7
  perpendicular L2 L4
  coincident P4 P6
  horizontal L8
  vertical L9
  horizontal L10
  vertical L11
  coincident L12 P270
  coincident L2 P271
  coincident L12 P273
  coincident L13 P281
  dimension "d134" distance P6 P7 = 2
  dimension "d135" distance P7 P8 = 0.75
  dimension "d136" distance P9 P10 = 0.05
  dimension "d143" distance P7 P272 = 0.1
  dimension "d154" distance P6 P280 = 0.1
sketch "Schizzo20" plane through (-1.6666, 149.9907, 0) normal (-0.0111, 0.9999, 0) x axis (0, 0, 1)
  curve K1 (-75.1807, 15.8361) -> (-75.1542, -12.4992)
  line L1 (75.1542, -12.4992) -> (-75.1542, -12.4992)
  curve K2 (75.1542, -12.4992) -> (75.1807, 15.8361)
  line L2 (-75.1807, 15.8361) -> (75.1807, 15.8361)
  curve K3 (75.1779, 14.3357) -> (75.1542, -10.9992)
  line L3 (-75.1542, -10.9992) -> (75.1542, -10.9992)
  curve K4 (-75.1542, -10.9992) -> (-75.1779, 14.3357)
  line L4 (75.1779, 14.3357) -> (-75.1779, 14.3357)
sweep "Sweep1" sketch "Schizzo19" TwistAngle 0 TaperAngle 0
sweep "Sweep2" sketch "Schizzo19" TwistAngle 0 TaperAngle 0
sketch "Schizzo10" plane through (12.4985, -0.1389, 0) normal (0.9999, -0.0111, 0) x axis (0, 0, -1)
  curve K1 (62.5, 5.1389) -> (62.9222, 5.1388)
  line L1 (75.0119, 148.3148) -> (62.9222, 5.1388)
  line L2 (-75.0119, 148.3148) -> (75.0119, 148.3148)
  line L3 (-62.9222, 5.1388) -> (-75.0119, 148.3148)
  curve K2 (-62.9222, 5.1388) -> (-62.5, 5.1389)
  line L4 (62.5, 5.1389) -> (-62.5, 5.1389)
  line L5 (-60.8243, 140.0874) -> (-57.379, 100.784)
  line L6 (-60.1722, 140.8503) -> (-60.1854, 140.8492)
  line L7 (-55.9651, 100.9062) -> (-59.4105, 140.2114)
  line L8 (-56.6816, 100.1451) -> (-56.6624, 100.1451)
  line L9 (-45.3183, 140.2067) -> (-42.5597, 100.7962)
  line L10 (-44.6546, 140.9597) -> (-44.6645, 140.959)
  line L11 (-41.1437, 100.894) -> (-43.9024, 140.3058)
  line L12 (-41.8614, 100.1451) -> (-41.842, 100.1451)
  line L13 (-23.2627, 140.1548) -> (-22.6248, 120.8232)
  line L14 (-22.58, 140.8808) -> (-22.5833, 140.8807)
  line L15 (-21.2163, 120.8694) -> (-21.8542, 140.2013)
  line L16 (-21.9252, 120.1463) -> (-21.916, 120.1463)
  line L17 (-0.7224, 140.1537) -> (-0.7224, 100.8451)
  line L18 (0.6802, 100.8451) -> (0.6802, 140.157)
  line L19 (-0.0224, 100.1451) -> (-0.0198, 100.1451)
  line L20 (19.2399, 19.5238) -> (19.8304, 37.4181)
  line L21 (18.5109, 18.8445) -> (18.5142, 18.8444)
  line L22 (18.4219, 37.4643) -> (17.8314, 19.5703)
  line L23 (19.1308, 38.1412) -> (19.1215, 38.1412)
  line L24 (36.8258, 140.19) -> (35.7668, 120.8847)
  line L25 (37.5728, 140.8531) -> (37.5662, 140.8535)
  line L26 (37.1773, 120.808) -> (38.2362, 140.1127)
  line L27 (36.4658, 120.1463) -> (36.4783, 120.1463)
  line L28 (40.5518, 60.7966) -> (42.9635, 97.3989)
  line L29 (39.8374, 60.1426) -> (39.8533, 60.1426)
  line L30 (41.5506, 97.4909) -> (39.1389, 60.8887)
  line L31 (42.265, 98.1449) -> (42.2491, 98.1449)
  line L32 (13.9558, 60.8272) -> (14.7608, 97.4295)
  line L33 (13.25, 60.1426) -> (13.2559, 60.1426)
  line L34 (13.3552, 97.4603) -> (12.5502, 60.858)
  line L35 (14.061, 98.1449) -> (14.055, 98.1449)
  line L36 (-22.5127, 117.423) -> (-21.3049, 80.8208)
  line L37 (-21.8038, 118.1462) -> (-21.813, 118.1462)
  line L38 (-19.8964, 80.8669) -> (-21.1041, 117.4692)
  line L39 (-20.6053, 80.1438) -> (-20.596, 80.1438)
  line L40 (6.5347, 117.4538) -> (6.1323, 80.8516)
  line L41 (7.2407, 118.1462) -> (7.2347, 118.1462)
  line L42 (7.5382, 80.8362) -> (7.9406, 117.4384)
  line L43 (6.8322, 80.1438) -> (6.8382, 80.1438)
  line L44 (-15.7526, 140.1687) -> (-14.8874, 100.8297)
  line L45 (-13.4818, 100.8605) -> (-14.347, 140.1996)
  line L46 (-14.1876, 100.1451) -> (-14.1816, 100.1451)
  line L47 (-21.1927, 77.4206) -> (-19.985, 40.8183)
  line L48 (-20.4838, 78.1437) -> (-20.4931, 78.1437)
  line L49 (-18.5764, 40.8645) -> (-19.7842, 77.4667)
  line L50 (-19.2853, 40.1413) -> (-19.2761, 40.1413)
  line L51 (52.1412, 57.5036) -> (48.7578, 18.906)
  line L52 (52.8578, 58.1425) -> (52.8386, 58.1425)
  line L53 (50.1715, 18.782) -> (53.5551, 57.3813)
  line L54 (49.3967, 18.1443) -> (49.4099, 18.1431)
  line L55 (47.0586, 77.4972) -> (44.2488, 40.895)
  line L56 (47.7758, 78.1437) -> (47.7566, 78.1437)
  line L57 (45.6639, 40.7878) -> (48.4737, 77.3901)
  line L58 (44.9468, 40.1413) -> (44.966, 40.1413)
  line L59 (-0.7224, 57.4424) -> (-0.7224, 20.0281)
  line L60 (-0.0198, 58.1425) -> (-0.0224, 58.1425)
  line L61 (0.6802, 20.0313) -> (0.6802, 57.4424)
  line L62 (59.3876, 140.1694) -> (55.9459, 100.9062)
  line L63 (60.1625, 140.8072) -> (60.1493, 140.8084)
  line L64 (57.3598, 100.784) -> (60.8014, 140.0455)
  line L65 (56.6432, 100.1451) -> (56.6624, 100.1451)
  line L66 (33.386, 77.482) -> (31.3782, 40.8797)
  line L67 (34.0975, 78.1437) -> (34.0849, 78.1437)
  line L68 (32.7886, 40.803) -> (34.7964, 77.4053)
  line L69 (32.0771, 40.1413) -> (32.0897, 40.1413)
  line L70 (53.8532, 60.7815) -> (57.0617, 97.3838)
  line L71 (53.1366, 60.1426) -> (53.1558, 60.1426)
  line L72 (55.6478, 97.506) -> (52.4393, 60.9038)
  line L73 (56.3644, 98.1449) -> (56.3451, 98.1449)
  line L74 (-34.8522, 77.4053) -> (-32.8444, 40.803)
  line L75 (-34.1407, 78.1437) -> (-34.1532, 78.1437)
  line L76 (-31.4339, 40.8797) -> (-33.4417, 77.482)
  line L77 (-32.1454, 40.1413) -> (-32.1328, 40.1413)
  line L78 (-7.9872, 117.4384) -> (-7.5848, 80.8362)
  line L79 (-7.2813, 118.1462) -> (-7.2873, 118.1462)
  line L80 (-6.1789, 80.8516) -> (-6.5814, 117.4538)
  line L81 (-6.8848, 80.1438) -> (-6.8789, 80.1438)
  line L82 (21.0618, 117.4692) -> (19.854, 80.8669)
  line L83 (21.7707, 118.1462) -> (21.7614, 118.1462)
  line L84 (21.2625, 80.8208) -> (22.4703, 117.423)
  line L85 (20.5536, 80.1438) -> (20.5629, 80.1438)
  line L86 (-30.7756, 140.1449) -> (-29.0447, 100.8143)
  line L87 (-30.1009, 140.8783) -> (-30.1042, 140.8782)
  line L88 (-27.6368, 100.8759) -> (-29.3677, 140.2069)
  line L89 (-28.3454, 100.1451) -> (-28.3362, 100.1451)
  line L90 (-52.4585, 60.9038) -> (-55.667, 97.506)
  line L91 (-53.1751, 60.1426) -> (-53.1558, 60.1426)
  line L92 (-57.0809, 97.3838) -> (-53.8724, 60.7815)
  line L93 (-56.3643, 98.1449) -> (-56.3836, 98.1449)
  line L94 (-12.602, 60.858) -> (-13.407, 97.4603)
  line L95 (-13.3078, 60.1426) -> (-13.3018, 60.1426)
  line L96 (-14.8126, 97.4295) -> (-14.0076, 60.8272)
  line L97 (-14.1068, 98.1449) -> (-14.1128, 98.1449)
  line L98 (44.3627, 140.1699) -> (41.7746, 100.8911)
  line L99 (45.1203, 140.8245) -> (45.1104, 140.8252)
  line L100 (43.1875, 100.7991) -> (45.7755, 140.0768)
  line L101 (42.4731, 100.1451) -> (42.489, 100.1451)
  line L102 (21.8113, 140.1836) -> (21.174, 120.8694)
  line L103 (22.5404, 140.8629) -> (22.5371, 140.8631)
  line L104 (22.5825, 120.8232) -> (23.2198, 140.1371)
  line L105 (21.8736, 120.1463) -> (21.8829, 120.1463)
  line L106 (6.8673, 19.8186) -> (7.0609, 37.4335)
  line L107 (5.6551, 37.4489) -> (5.4614, 19.8341)
  line L108 (6.361, 38.1412) -> (6.355, 38.1412)
  line L109 (-17.8744, 19.588) -> (-18.4643, 37.4643)
  line L110 (-18.5571, 18.8621) -> (-18.5538, 18.8622)
  line L111 (-19.8728, 37.4181) -> (-19.2829, 19.5415)
  line L112 (-19.1639, 38.1412) -> (-19.1731, 38.1412)
  line L113 (-38.2924, 140.1197) -> (-37.233, 120.808)
  line L114 (-37.6224, 140.8606) -> (-37.629, 140.8602)
  line L115 (-35.8226, 120.8847) -> (-36.8819, 140.1971)
  line L116 (-36.5341, 120.1463) -> (-36.5215, 120.1463)
  line L117 (-53.5743, 57.3813) -> (-50.1944, 18.824)
  line L118 (-52.8578, 58.1425) -> (-52.877, 58.1425)
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sketch "Schizzo11" plane through (13.3509, 76.5832, 0) normal (0.9999, -0.0111, 0) x axis (0, 0, -1)
chamfer "Smusso4" distance 1
rectangular_pattern "Serie R" countU 14 uSpaceDistance 110 vSpaceDistance 0
fillet "Raccordo5" radius 12
fillet "Raccordo6" radius 8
